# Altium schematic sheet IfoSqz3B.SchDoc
size C; Engineer: Daniel Sigg; DocumentNumber: 7; SheetNumber: 19; SheetTotal: 33
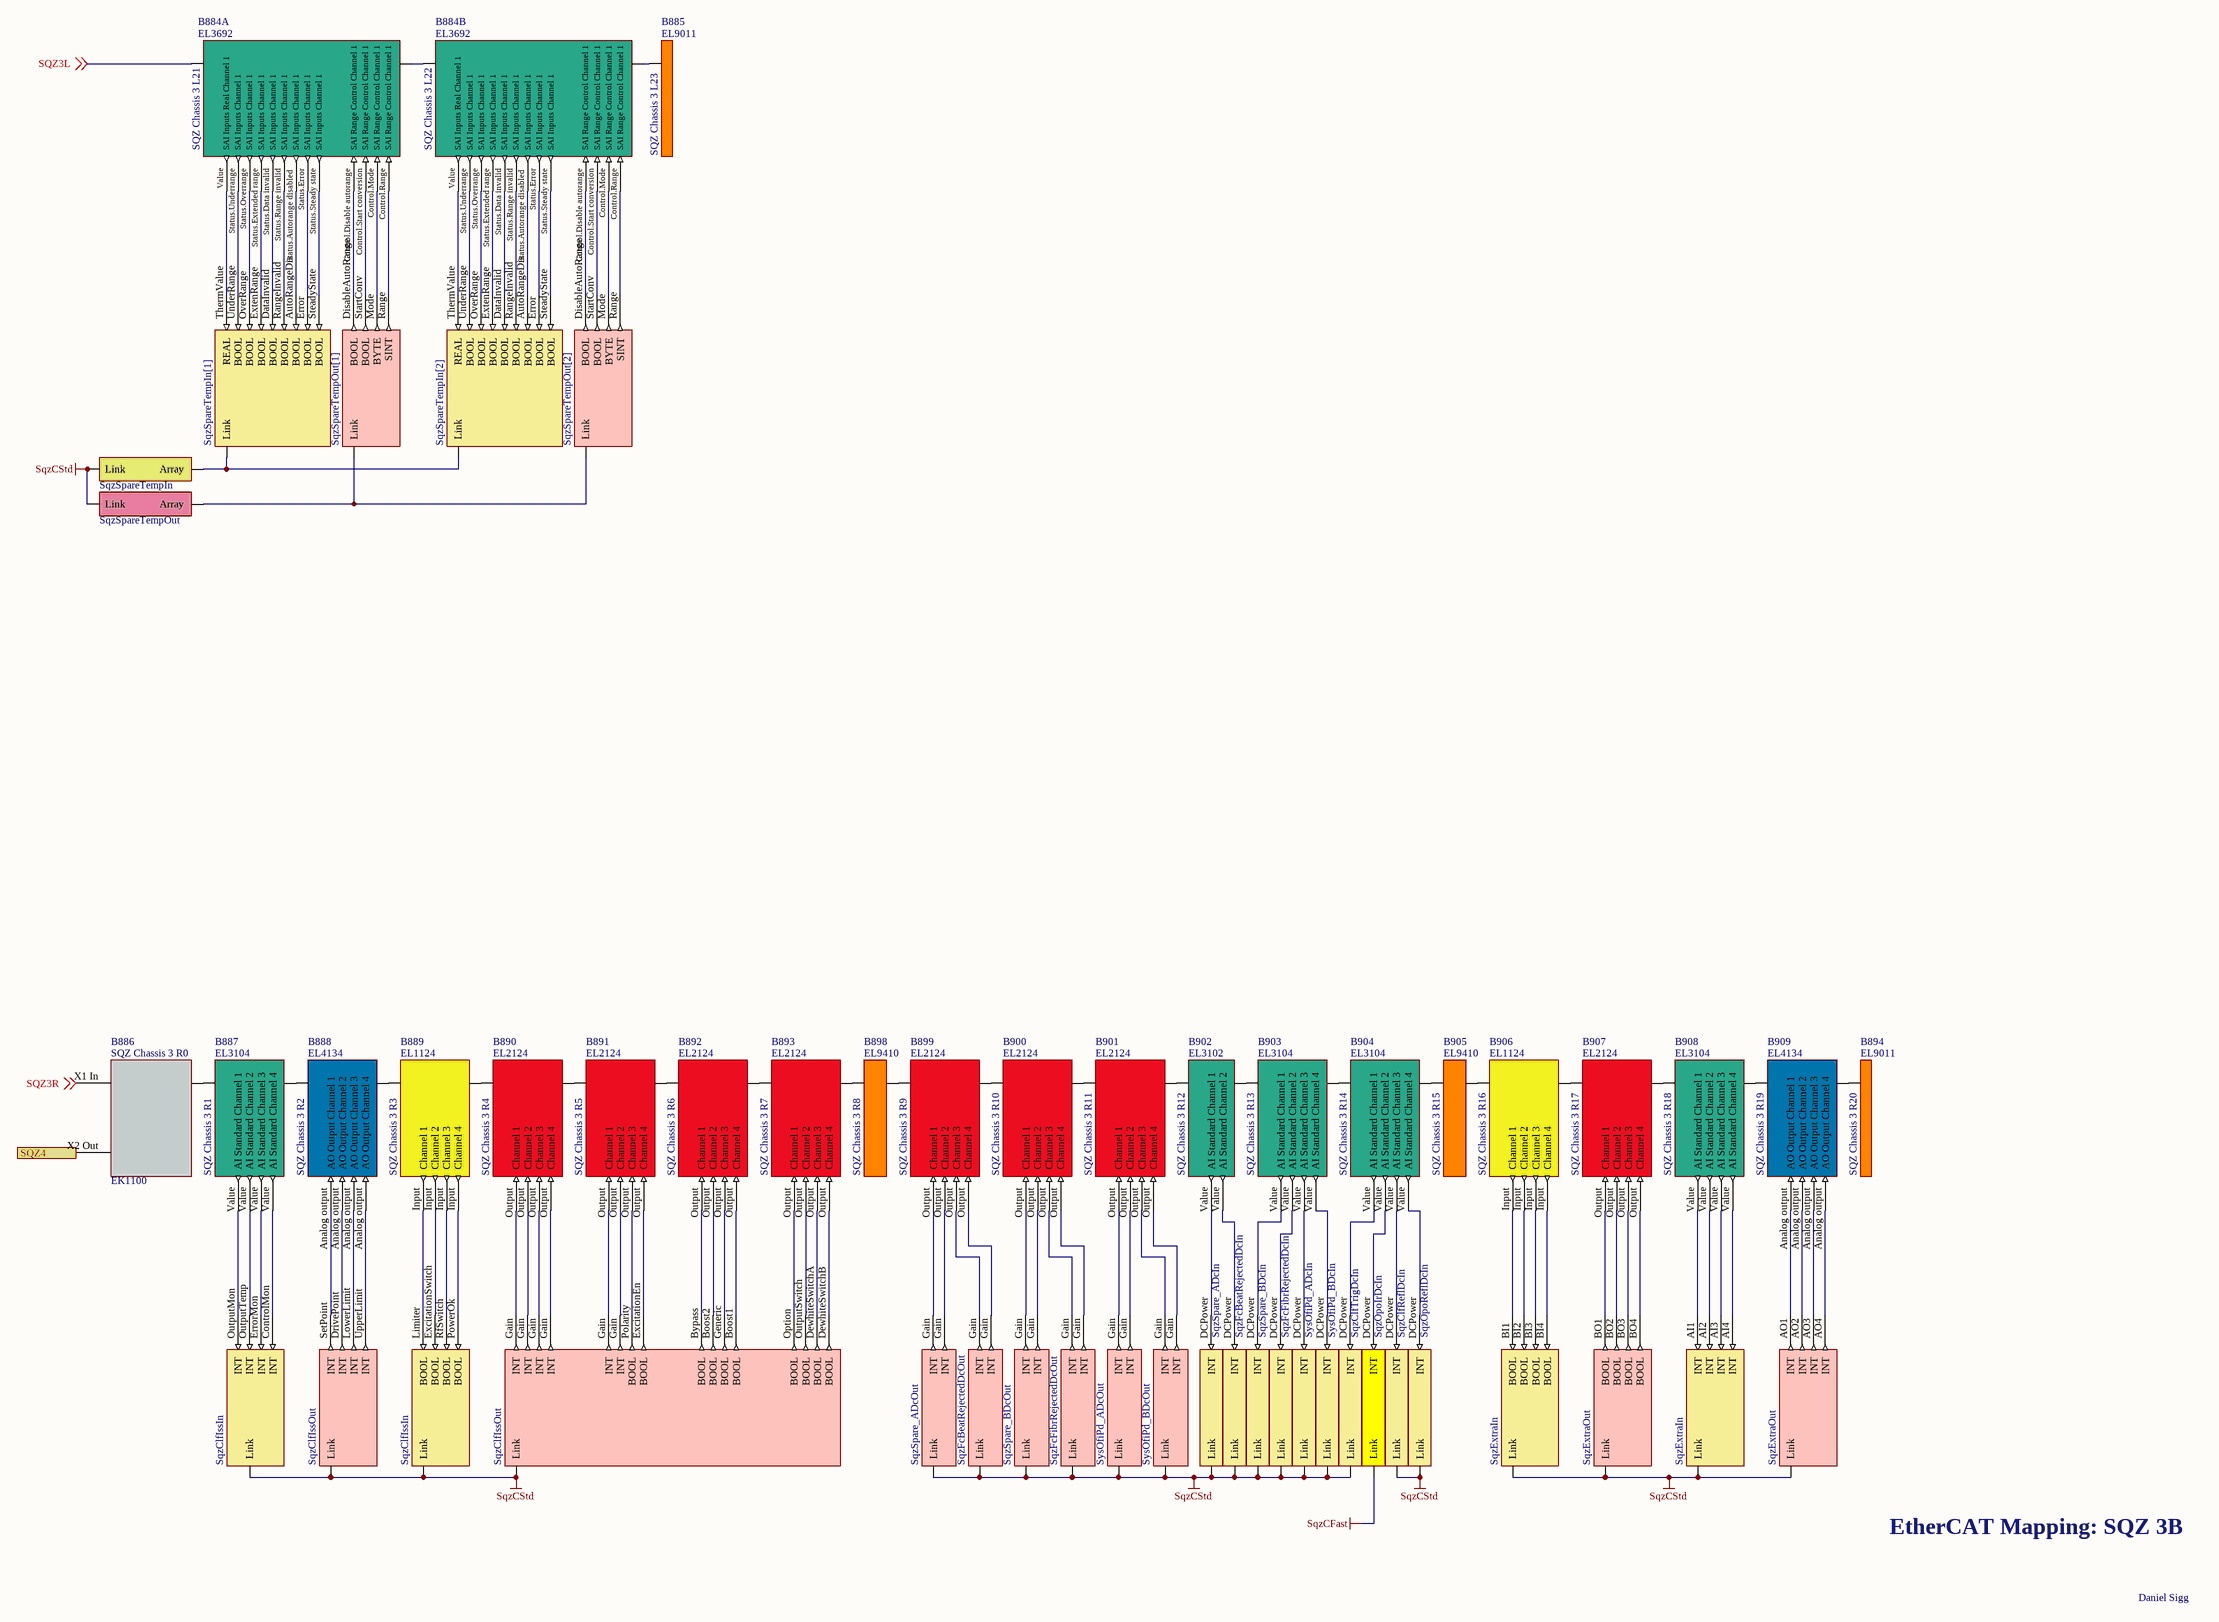
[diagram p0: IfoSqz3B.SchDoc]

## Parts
B884A  SQZ Chassis 3 L21  Part Number: EL3692  (mechanical)
B884B  SQZ Chassis 3 L22  Part Number: EL3692  (mechanical)
B885  SQZ Chassis 3 L23  Part Number: EL9011  (mechanical)
B886  SQZ Chassis 3 R0  Part Number: EK1100
B887  SQZ Chassis 3 R1  Part Number: EL3104  (mechanical)
B888  SQZ Chassis 3 R2  Part Number: EL4134  (mechanical)
B889  SQZ Chassis 3 R3  Part Number: EL1124  (mechanical)
B890  SQZ Chassis 3 R4  Part Number: EL2124  (mechanical)
B891  SQZ Chassis 3 R5  Part Number: EL2124  (mechanical)
B892  SQZ Chassis 3 R6  Part Number: EL2124  (mechanical)
B893  SQZ Chassis 3 R7  Part Number: EL2124  (mechanical)
B894  SQZ Chassis 3 R20  Part Number: EL9011  (mechanical)
B898  SQZ Chassis 3 R8  Part Number: EL9410  (mechanical)
B899  SQZ Chassis 3 R9  Part Number: EL2124  (mechanical)
B900  SQZ Chassis 3 R10  Part Number: EL2124  (mechanical)
B901  SQZ Chassis 3 R11  Part Number: EL2124  (mechanical)
B902  SQZ Chassis 3 R12  Part Number: EL3102  (mechanical)
B903  SQZ Chassis 3 R13  Part Number: EL3104  (mechanical)
B904  SQZ Chassis 3 R14  Part Number: EL3104  (mechanical)
B905  SQZ Chassis 3 R15  Part Number: EL9410  (mechanical)
B906  SQZ Chassis 3 R16  Part Number: EL1124  (mechanical)
B907  SQZ Chassis 3 R17  Part Number: EL2124  (mechanical)
B908  SQZ Chassis 3 R18  Part Number: EL3104  (mechanical)
B909  SQZ Chassis 3 R19  Part Number: EL4134  (mechanical)
V410  SqzClfIssIn  (parts A,B of 2)  (no BOM)
V411  SqzClfIssOut  (parts A,B of 2)  (no BOM)
V701  SqzSpareTempIn[1]  (no BOM)
V702  SqzSpareTempOut[1]  (no BOM)
V703  SqzSpareTempIn[2]  (no BOM)
V704  SqzSpareTempOut[2]  (no BOM)
V705  SqzSpareTempIn  (no BOM)
V706  SqzSpareTempOut  (no BOM)
V722  SqzSpare_ADcOut  (no BOM)
V723  SqzFcBeatRejectedDcOut  (no BOM)
V724  SqzFcFibrRejectedDcOut  (no BOM)
V725  SqzSpare_BDcOut  (no BOM)
V726  SysOfiPd_ADcOut  (no BOM)
V727  SysOfiPd_BDcOut  (no BOM)
V728  SqzSpare_ADcIn  (no BOM)
V729  SqzFcBeatRejectedDcIn  (no BOM)
V730  SqzFcFibrRejectedDcIn  (no BOM)
V731  SqzSpare_BDcIn  (no BOM)
V732  SysOfiPd_ADcIn  (no BOM)
V733  SysOfiPd_BDcIn  (no BOM)
V734  SqzClfTrigDcIn  (no BOM)
V735  SqzOpoIrDcIn  (no BOM)
V736  SqzClfReflDcIn  (no BOM)
V737  SqzOpoReflDcIn  (no BOM)
V738  SqzExtraIn  (parts A,B of 2)  (no BOM)
V739  SqzExtraOut  (parts A,B of 2)  (no BOM)

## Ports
SQZ4

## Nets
SqzCFast: V735.1(Link)
SqzCStd: V410.0(Link) V410.1(Link) V411.0(Link) V411.1(Link) V705.?1(Link) V706.?1(Link) V722.0(Link) V723.0(Link) V724.0(Link) V725.0(Link) V726.0(Link) V727.0(Link) V728.1(Link) V729.1(Link) V730.1(Link) V731.1(Link) V732.1(Link) V733.1(Link) V734.1(Link) V736.1(Link) V737.1(Link) V738.0(Link) V738.1(Link) V739.0(Link) V739.1(Link)
SQZ3L: B884A.Ebus(A) ; off-sheet SQZ3L
SQZ3R: B886.X1_In(A) ; off-sheet SQZ3R
SQZ4: B886.X2_Out(C) ; port SQZ4
NetB884A_Control.Disable autorange: B884A.Control.Disable_autorange(SAI_Range_Control_Channel_1) V702.DisableAutoRange(BOOL)
NetB884A_Control.Mode: B884A.Control.Mode(SAI_Range_Control_Channel_1) V702.Mode(BYTE)
NetB884A_Control.Range: B884A.Control.Range(SAI_Range_Control_Channel_1) V702.Range(SINT)
NetB884A_Control.Start conversion: B884A.Control.Start_conversion(SAI_Range_Control_Channel_1) V702.StartConv(BOOL)
NetB884A_Ebus: B884A.Ebus(B) B884B.Ebus(A)
NetB884A_Status.Autorange disabled: B884A.Status.Autorange_disabled(SAI_Inputs_Channel_1) V701.AutoRangeDis(BOOL)
NetB884A_Status.Data invalid: B884A.Status.Data_invalid(SAI_Inputs_Channel_1) V701.DataInvalid(BOOL)
NetB884A_Status.Error: B884A.Status.Error(SAI_Inputs_Channel_1) V701.Error(BOOL)
NetB884A_Status.Extended range: B884A.Status.Extended_range(SAI_Inputs_Channel_1) V701.ExtenRange(BOOL)
NetB884A_Status.Overrange: B884A.Status.Overrange(SAI_Inputs_Channel_1) V701.OverRange(BOOL)
NetB884A_Status.Range invalid: B884A.Status.Range_invalid(SAI_Inputs_Channel_1) V701.RangeInvalid(BOOL)
NetB884A_Status.Steady state: B884A.Status.Steady_state(SAI_Inputs_Channel_1) V701.SteadyState(BOOL)
NetB884A_Status.Underrange: B884A.Status.Underrange(SAI_Inputs_Channel_1) V701.UnderRange(BOOL)
NetB884A_Value: B884A.Value(SAI_Inputs_Real_Channel_1) V701.ThermValue(REAL)
NetB884B_Control.Disable autorange: B884B.Control.Disable_autorange(SAI_Range_Control_Channel_1) V704.DisableAutoRange(BOOL)
NetB884B_Control.Mode: B884B.Control.Mode(SAI_Range_Control_Channel_1) V704.Mode(BYTE)
NetB884B_Control.Range: B884B.Control.Range(SAI_Range_Control_Channel_1) V704.Range(SINT)
NetB884B_Control.Start conversion: B884B.Control.Start_conversion(SAI_Range_Control_Channel_1) V704.StartConv(BOOL)
NetB884B_Ebus: B884B.Ebus(B) B885.Ebus(A)
NetB884B_Status.Autorange disabled: B884B.Status.Autorange_disabled(SAI_Inputs_Channel_1) V703.AutoRangeDis(BOOL)
NetB884B_Status.Data invalid: B884B.Status.Data_invalid(SAI_Inputs_Channel_1) V703.DataInvalid(BOOL)
NetB884B_Status.Error: B884B.Status.Error(SAI_Inputs_Channel_1) V703.Error(BOOL)
NetB884B_Status.Extended range: B884B.Status.Extended_range(SAI_Inputs_Channel_1) V703.ExtenRange(BOOL)
NetB884B_Status.Overrange: B884B.Status.Overrange(SAI_Inputs_Channel_1) V703.OverRange(BOOL)
NetB884B_Status.Range invalid: B884B.Status.Range_invalid(SAI_Inputs_Channel_1) V703.RangeInvalid(BOOL)
NetB884B_Status.Steady state: B884B.Status.Steady_state(SAI_Inputs_Channel_1) V703.SteadyState(BOOL)
NetB884B_Status.Underrange: B884B.Status.Underrange(SAI_Inputs_Channel_1) V703.UnderRange(BOOL)
NetB884B_Value: B884B.Value(SAI_Inputs_Real_Channel_1) V703.ThermValue(REAL)
NetB886_Ebus: B886.Ebus(B) B887.Ebus(A)
NetB887_Ebus: B887.Ebus(B) B888.Ebus(A)
NetB887_Value: B887.Value(AI_Standard_Channel_1) V410.OutputMon(INT)
NetB887_Value: B887.Value(AI_Standard_Channel_2) V410.OutputTemp(INT)  [a separate net that carries the same name]
NetB887_Value: B887.Value(AI_Standard_Channel_3) V410.ErrorMon(INT)  [a separate net that carries the same name]
NetB887_Value: B887.Value(AI_Standard_Channel_4) V410.ControlMon(INT)  [a separate net that carries the same name]
NetB888_Analog output: B888.Analog_output(AO_Output_Channel_1) V411.SetPoint(INT)
NetB888_Analog output: B888.Analog_output(AO_Output_Channel_2) V411.DrivePoint(INT)  [a separate net that carries the same name]
NetB888_Analog output: B888.Analog_output(AO_Output_Channel_3) V411.LowerLimit(INT)  [a separate net that carries the same name]
NetB888_Analog output: B888.Analog_output(AO_Output_Channel_4) V411.UpperLimit(INT)  [a separate net that carries the same name]
NetB888_Ebus: B888.Ebus(B) B889.Ebus(A)
NetB889_Ebus: B889.Ebus(B) B890.Ebus(A)
NetB889_Input: B889.Input(Channel_1) V410.Limiter(BOOL)
NetB889_Input: B889.Input(Channel_2) V410.ExcitationSwitch(BOOL)  [a separate net that carries the same name]
NetB889_Input: B889.Input(Channel_3) V410.RfSwitch(BOOL)  [a separate net that carries the same name]
NetB889_Input: B889.Input(Channel_4) V410.PowerOk(BOOL)  [a separate net that carries the same name]
NetB890_Ebus: B890.Ebus(B) B891.Ebus(A)
NetB890_Output: B890.Output(Channel_1) V411.Gain(INT)
NetB890_Output: B890.Output(Channel_2) V411.Gain(INT)  [a separate net that carries the same name]
NetB890_Output: B890.Output(Channel_3) V411.Gain(INT)  [a separate net that carries the same name]
NetB890_Output: B890.Output(Channel_4) V411.Gain(INT)  [a separate net that carries the same name]
NetB891_Ebus: B891.Ebus(B) B892.Ebus(A)
NetB891_Output: B891.Output(Channel_1) V411.Gain(INT)
NetB891_Output: B891.Output(Channel_2) V411.Gain(INT)  [a separate net that carries the same name]
NetB891_Output: B891.Output(Channel_3) V411.Polarity(BOOL)  [a separate net that carries the same name]
NetB891_Output: B891.Output(Channel_4) V411.ExcitationEn(BOOL)  [a separate net that carries the same name]
NetB892_Ebus: B892.Ebus(B) B893.Ebus(A)
NetB892_Output: B892.Output(Channel_1) V411.Bypass(BOOL)
NetB892_Output: B892.Output(Channel_2) V411.Boost2(BOOL)  [a separate net that carries the same name]
NetB892_Output: B892.Output(Channel_3) V411.Generic(BOOL)  [a separate net that carries the same name]
NetB892_Output: B892.Output(Channel_4) V411.Boost1(BOOL)  [a separate net that carries the same name]
NetB893_Ebus: B893.Ebus(B) B898.Ebus(A)
NetB893_Output: B893.Output(Channel_1) V411.Option(BOOL)
NetB893_Output: B893.Output(Channel_2) V411.OutputSwitch(BOOL)  [a separate net that carries the same name]
NetB893_Output: B893.Output(Channel_3) V411.DewhiteSwitchA(BOOL)  [a separate net that carries the same name]
NetB893_Output: B893.Output(Channel_4) V411.DewhiteSwitchB(BOOL)  [a separate net that carries the same name]
NetB894_Ebus: B894.Ebus(A) B909.Ebus(B)
NetB898_Ebus: B898.Ebus(B) B899.Ebus(A)
NetB899_Ebus: B899.Ebus(B) B900.Ebus(A)
NetB899_Output: B899.Output(Channel_1) V722.Gain(INT)
NetB899_Output: B899.Output(Channel_2) V722.Gain(INT)  [a separate net that carries the same name]
NetB899_Output: B899.Output(Channel_3) V723.Gain(INT)  [a separate net that carries the same name]
NetB899_Output: B899.Output(Channel_4) V723.Gain(INT)  [a separate net that carries the same name]
NetB900_Ebus: B900.Ebus(B) B901.Ebus(A)
NetB900_Output: B900.Output(Channel_1) V725.Gain(INT)
NetB900_Output: B900.Output(Channel_2) V725.Gain(INT)  [a separate net that carries the same name]
NetB900_Output: B900.Output(Channel_3) V724.Gain(INT)  [a separate net that carries the same name]
NetB900_Output: B900.Output(Channel_4) V724.Gain(INT)  [a separate net that carries the same name]
NetB901_Ebus: B901.Ebus(B) B902.Ebus(A)
NetB901_Output: B901.Output(Channel_1) V726.Gain(INT)
NetB901_Output: B901.Output(Channel_2) V726.Gain(INT)  [a separate net that carries the same name]
NetB901_Output: B901.Output(Channel_3) V727.Gain(INT)  [a separate net that carries the same name]
NetB901_Output: B901.Output(Channel_4) V727.Gain(INT)  [a separate net that carries the same name]
NetB902_Ebus: B902.Ebus(B) B903.Ebus(A)
NetB902_Value: B902.Value(AI_Standard_Channel_1) V728.DCPower(INT)
NetB902_Value: B902.Value(AI_Standard_Channel_2) V729.DCPower(INT)  [a separate net that carries the same name]
NetB903_Ebus: B903.Ebus(B) B904.Ebus(A)
NetB903_Value: B903.Value(AI_Standard_Channel_1) V731.DCPower(INT)
NetB903_Value: B903.Value(AI_Standard_Channel_2) V730.DCPower(INT)  [a separate net that carries the same name]
NetB903_Value: B903.Value(AI_Standard_Channel_3) V732.DCPower(INT)  [a separate net that carries the same name]
NetB903_Value: B903.Value(AI_Standard_Channel_4) V733.DCPower(INT)  [a separate net that carries the same name]
NetB904_Ebus: B904.Ebus(B) B905.Ebus(A)
NetB904_Value: B904.Value(AI_Standard_Channel_1) V734.DCPower(INT)
NetB904_Value: B904.Value(AI_Standard_Channel_2) V735.DCPower(INT)  [a separate net that carries the same name]
NetB904_Value: B904.Value(AI_Standard_Channel_3) V736.DCPower(INT)  [a separate net that carries the same name]
NetB904_Value: B904.Value(AI_Standard_Channel_4) V737.DCPower(INT)  [a separate net that carries the same name]
NetB905_Ebus: B905.Ebus(B) B906.Ebus(A)
NetB906_Ebus: B906.Ebus(B) B907.Ebus(A)
NetB906_Input: B906.Input(Channel_1) V738.BI1(BOOL)
NetB906_Input: B906.Input(Channel_2) V738.BI2(BOOL)  [a separate net that carries the same name]
NetB906_Input: B906.Input(Channel_3) V738.BI3(BOOL)  [a separate net that carries the same name]
NetB906_Input: B906.Input(Channel_4) V738.BI4(BOOL)  [a separate net that carries the same name]
NetB907_Ebus: B907.Ebus(B) B908.Ebus(A)
NetB907_Output: B907.Output(Channel_1) V739.BO1(BOOL)
NetB907_Output: B907.Output(Channel_2) V739.BO2(BOOL)  [a separate net that carries the same name]
NetB907_Output: B907.Output(Channel_3) V739.BO3(BOOL)  [a separate net that carries the same name]
NetB907_Output: B907.Output(Channel_4) V739.BO4(BOOL)  [a separate net that carries the same name]
NetB908_Ebus: B908.Ebus(B) B909.Ebus(A)
NetB908_Value: B908.Value(AI_Standard_Channel_1) V738.AI1(INT)
NetB908_Value: B908.Value(AI_Standard_Channel_2) V738.AI2(INT)  [a separate net that carries the same name]
NetB908_Value: B908.Value(AI_Standard_Channel_3) V738.AI3(INT)  [a separate net that carries the same name]
NetB908_Value: B908.Value(AI_Standard_Channel_4) V738.AI4(INT)  [a separate net that carries the same name]
NetB909_Analog output: B909.Analog_output(AO_Output_Channel_1) V739.AO1(INT)
NetB909_Analog output: B909.Analog_output(AO_Output_Channel_2) V739.AO2(INT)  [a separate net that carries the same name]
NetB909_Analog output: B909.Analog_output(AO_Output_Channel_3) V739.AO3(INT)  [a separate net that carries the same name]
NetB909_Analog output: B909.Analog_output(AO_Output_Channel_4) V739.AO4(INT)  [a separate net that carries the same name]
NetV701_1: V701.1(Link) V703.1(Link) V705.?2(Array)
NetV702_1: V702.1(Link) V704.1(Link) V706.?2(Array)

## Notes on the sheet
- EtherCAT Mapping: SQZ 3B
- Daniel Sigg

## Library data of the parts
B884A = TerminalEL3692-1chn: EtherCAT Terminal EL3692 1-chn Resistance Measurement; Rail: Left; BoxNextB: HCCQCWHL; BoxPrev: FHTRRYRM; PortPrevFull: 1141/B; PortPrevShort: B; Fullname: TIID^Vertex Squeezer (EtherCAT)^SQZ Chassis 3 L0 (EK1101)^SQZ Chassis 3 L21 (EL3692); BoxAddr: 1142; PDO Inputs: 0x1A00,0x1A02; PDO Outputs: 0x1600; Disabled: False
B884B = TerminalEL3692-1chn: EtherCAT Terminal EL3692 1-chn Resistance Measurement; Rail: Left; BoxNextB: CYSUGKJU; BoxPrev: BXXLOSJW; PortPrevFull: 1142/B; PortPrevShort: B; Fullname: TIID^Vertex Squeezer (EtherCAT)^SQZ Chassis 3 L0 (EK1101)^SQZ Chassis 3 L22 (EL3692); BoxAddr: 1143; PDO Inputs: 0x1A00,0x1A02; PDO Outputs: 0x1600; Disabled: False
B885 = TerminalEL9011: EtherCAT Terminal EL9011 End; BoxType: TerminalPassive; Rail: Left; BoxPrev: HCCQCWHL; PortPrevShort: B; Fullname: TIID^Vertex Squeezer (EtherCAT)^SQZ Chassis 3 L0 (EK1101)^SQZ Chassis 3 L23 (EL9011); Disabled: False
B886 = CouplerEK1100: EtherCAT Coupler; Rail: Right; BoxNextB: LMNHRKFK; BoxNextC: BCNOLNHC; BoxPrev: VQWTFMVH; PortPrevFull: 1144/C; PortPrevShort: C 'X2 Out'; Fullname: TIID^Vertex Squeezer (EtherCAT)^SQZ Chassis 3 R0 (EK1100); BoxPorts: Junction; BoxAddr: 1168; Disabled: False
B887 = TerminalEL3104: EtherCAT Terminal EL3104 4-chn Analog Input; Rail: Right; BoxNextB: SAJIWMHJ; BoxPrev: BKUDMEPV; PortPrevFull: 1168/B; PortPrevShort: B; Fullname: TIID^Vertex Squeezer (EtherCAT)^SQZ Chassis 3 R0 (EK1100)^SQZ Chassis 3 R1 (EL3104); BoxAddr: 1169; Disabled: False
B888 = TerminalEL4134: EtherCAT Terminal EL4134 4-chn Analog Ouput; Rail: Right; BoxNextB: JGBHBNGR; BoxPrev: LMNHRKFK; PortPrevFull: 1169/B; PortPrevShort: B; Fullname: TIID^Vertex Squeezer (EtherCAT)^SQZ Chassis 3 R0 (EK1100)^SQZ Chassis 3 R2 (EL4134); BoxAddr: 1170; Disabled: False
B889 = TerminalEL1124: EtherCAT Terminal EL1124 4-chn Digital Input; Rail: Right; BoxNextB: VKBNNKDD; BoxPrev: SAJIWMHJ; PortPrevFull: 1170/B; PortPrevShort: B; Fullname: TIID^Vertex Squeezer (EtherCAT)^SQZ Chassis 3 R0 (EK1100)^SQZ Chassis 3 R3 (EL1124); BoxAddr: 1171; Disabled: False
B890 = TerminalEL2124: EtherCAT Terminal EL2124 4-chn Digital Ouput; Rail: Right; BoxNextB: CQYTOJCV; BoxPrev: JGBHBNGR; PortPrevFull: 1171/B; PortPrevShort: B; Fullname: TIID^Vertex Squeezer (EtherCAT)^SQZ Chassis 3 R0 (EK1100)^SQZ Chassis 3 R4 (EL2124); BoxAddr: 1172; Disabled: False
B891 = TerminalEL2124: EtherCAT Terminal EL2124 4-chn Digital Ouput; Rail: Right; BoxNextB: GUINYQMW; BoxPrev: VKBNNKDD; PortPrevFull: 1172/B; PortPrevShort: B; Fullname: TIID^Vertex Squeezer (EtherCAT)^SQZ Chassis 3 R0 (EK1100)^SQZ Chassis 3 R5 (EL2124); BoxAddr: 1173; Disabled: False
B892 = TerminalEL2124: EtherCAT Terminal EL2124 4-chn Digital Ouput; Rail: Right; BoxNextB: HMWVQJTD; BoxPrev: CQYTOJCV; PortPrevFull: 1173/B; PortPrevShort: B; Fullname: TIID^Vertex Squeezer (EtherCAT)^SQZ Chassis 3 R0 (EK1100)^SQZ Chassis 3 R6 (EL2124); BoxAddr: 1174; Disabled: False
B893 = TerminalEL2124: EtherCAT Terminal EL2124 4-chn Digital Ouput; Rail: Right; BoxNextB: EWXBFFSC; BoxPrev: GUINYQMW; PortPrevFull: 1174/B; PortPrevShort: B; Fullname: TIID^Vertex Squeezer (EtherCAT)^SQZ Chassis 3 R0 (EK1100)^SQZ Chassis 3 R7 (EL2124); BoxAddr: 1175; Disabled: False
B894 = TerminalEL9011: EtherCAT Terminal EL9011 End; BoxType: TerminalPassive; Rail: Right; BoxPrev: REDTJCGQ; PortPrevShort: B; Fullname: TIID^Vertex Squeezer (EtherCAT)^SQZ Chassis 3 R0 (EK1100)^SQZ Chassis 3 R20 (EL9011); Disabled: False
B898 = TerminalEL9410: EtherCAT Terminal EL9410 Power; Rail: Right; BoxNextB: TDWNLRLC; BoxPrev: HMWVQJTD; PortPrevFull: 1175/B; PortPrevShort: B; Fullname: TIID^Vertex Squeezer (EtherCAT)^SQZ Chassis 3 R0 (EK1100)^SQZ Chassis 3 R8 (EL9410); BoxAddr: 1176; Disabled: False
B899 = TerminalEL2124: EtherCAT Terminal EL2124 4-chn Digital Ouput; Rail: Right; BoxNextB: JKJTFGCV; BoxPrev: EWXBFFSC; PortPrevFull: 1176/B; PortPrevShort: B; Fullname: TIID^Vertex Squeezer (EtherCAT)^SQZ Chassis 3 R0 (EK1100)^SQZ Chassis 3 R9 (EL2124); BoxAddr: 1177; Disabled: False
B900 = TerminalEL2124: EtherCAT Terminal EL2124 4-chn Digital Ouput; Rail: Right; BoxNextB: YYBAPAKS; BoxPrev: TDWNLRLC; PortPrevFull: 1177/B; PortPrevShort: B; Fullname: TIID^Vertex Squeezer (EtherCAT)^SQZ Chassis 3 R0 (EK1100)^SQZ Chassis 3 R10 (EL2124); BoxAddr: 1178; Disabled: False
B901 = TerminalEL2124: EtherCAT Terminal EL2124 4-chn Digital Ouput; Rail: Right; BoxNextB: KULEGXXY; BoxPrev: JKJTFGCV; PortPrevFull: 1178/B; PortPrevShort: B; Fullname: TIID^Vertex Squeezer (EtherCAT)^SQZ Chassis 3 R0 (EK1100)^SQZ Chassis 3 R11 (EL2124); BoxAddr: 1179; Disabled: False
B902 = TerminalEL3102: EtherCAT Terminal EL3102 2-chn Analog Input; Rail: Right; BoxNextB: QOIJDIEC; BoxPrev: YYBAPAKS; PortPrevFull: 1179/B; PortPrevShort: B; Fullname: TIID^Vertex Squeezer (EtherCAT)^SQZ Chassis 3 R0 (EK1100)^SQZ Chassis 3 R12 (EL3102); BoxAddr: 1180; Disabled: False
B903 = TerminalEL3104: EtherCAT Terminal EL3104 4-chn Analog Input; Rail: Right; BoxNextB: XSWHLOWF; BoxPrev: KULEGXXY; PortPrevFull: 1180/B; PortPrevShort: B; Fullname: TIID^Vertex Squeezer (EtherCAT)^SQZ Chassis 3 R0 (EK1100)^SQZ Chassis 3 R13 (EL3104); BoxAddr: 1181; Disabled: False
B904 = TerminalEL3104: EtherCAT Terminal EL3104 4-chn Analog Input; Rail: Right; BoxNextB: DXXDEXAW; BoxPrev: QOIJDIEC; PortPrevFull: 1181/B; PortPrevShort: B; Fullname: TIID^Vertex Squeezer (EtherCAT)^SQZ Chassis 3 R0 (EK1100)^SQZ Chassis 3 R14 (EL3104); BoxAddr: 1182; Disabled: False
B905 = TerminalEL9410: EtherCAT Terminal EL9410 Power; Rail: Right; BoxNextB: LQYWWYRA; BoxPrev: XSWHLOWF; PortPrevFull: 1182/B; PortPrevShort: B; Fullname: TIID^Vertex Squeezer (EtherCAT)^SQZ Chassis 3 R0 (EK1100)^SQZ Chassis 3 R15 (EL9410); BoxAddr: 1183; Disabled: False
B906 = TerminalEL1124: EtherCAT Terminal EL1124 4-chn Digital Input; Rail: Right; BoxNextB: KAAFGPDB; BoxPrev: DXXDEXAW; PortPrevFull: 1183/B; PortPrevShort: B; Fullname: TIID^Vertex Squeezer (EtherCAT)^SQZ Chassis 3 R0 (EK1100)^SQZ Chassis 3 R16 (EL1124); BoxAddr: 1184; Disabled: False
B907 = TerminalEL2124: EtherCAT Terminal EL2124 4-chn Digital Ouput; Rail: Right; BoxNextB: YRGWWXTI; BoxPrev: LQYWWYRA; PortPrevFull: 1184/B; PortPrevShort: B; Fullname: TIID^Vertex Squeezer (EtherCAT)^SQZ Chassis 3 R0 (EK1100)^SQZ Chassis 3 R17 (EL2124); BoxAddr: 1185; Disabled: False
B908 = TerminalEL3104: EtherCAT Terminal EL3104 4-chn Analog Input; Rail: Right; BoxNextB: REDTJCGQ; BoxPrev: KAAFGPDB; PortPrevFull: 1185/B; PortPrevShort: B; Fullname: TIID^Vertex Squeezer (EtherCAT)^SQZ Chassis 3 R0 (EK1100)^SQZ Chassis 3 R18 (EL3104); BoxAddr: 1186; Disabled: False
B909 = TerminalEL4134: EtherCAT Terminal EL4134 4-chn Analog Ouput; Rail: Right; BoxNextB: RXFIDCPJ; BoxPrev: YRGWWXTI; PortPrevFull: 1186/B; PortPrevShort: B; Fullname: TIID^Vertex Squeezer (EtherCAT)^SQZ Chassis 3 R0 (EK1100)^SQZ Chassis 3 R19 (EL4134); BoxAddr: 1187; Disabled: False
V410 = Iss_AomServoInStruct: AomServoInStruct; BoxType: Variable; Instance: H1SqzCorner Instance; PLC: H1SqzCorner; Task: SqzCStd
V411 = Iss_AomServoOutStruct: AomServoOutStruct; BoxType: Variable; Instance: H1SqzCorner Instance; PLC: H1SqzCorner; Task: SqzCStd
V701 V703 = TECController_ThermistorInStruct: ThermistorInStruct; BoxType: Variable; Instance: H1SqzCorner Instance; PLC: H1SqzCorner; Task: SqzCStd
V702 V704 = TECController_ThermistorOutStruct: ThermistorOutStruct; BoxType: Variable; Instance: H1SqzCorner Instance; PLC: H1SqzCorner; Task: SqzCStd
V705 = ArrayAggregatorIn: Array [1..2] Of ThermistorInStruct; Instance: H1SqzCorner Instance; PLC: H1SqzCorner; Task: SqzCStd; Lower Bound: 1; Upper Bound: 2
V706 = ArrayAggregatorOut: Array [1..2] Of ThermistorOutStruct; Instance: H1SqzCorner Instance; PLC: H1SqzCorner; Task: SqzCStd; Lower Bound: 1; Upper Bound: 2
V722-V727 = DCPower_DCPowerOutStruct: DCPowerOutStruct; BoxType: Variable; Instance: H1SqzCorner Instance; PLC: H1SqzCorner; Task: SqzCStd
V728-V734 V736 V737 = DCPower_DCPowerInStruct: DCPowerInStruct; BoxType: Variable; Instance: H1SqzCorner Instance; PLC: H1SqzCorner; Task: SqzCStd
V735 = DCPower_DCPowerFastInStruct: DCPowerInStruct; BoxType: Variable; Instance: H1SqzCorner Instance; PLC: H1SqzCorner; Task: SqzCFast
V738 = Auxiliary_AuxiliaryInStruct: AuxiliaryInStruct; BoxType: Variable; Instance: H1SqzCorner Instance; PLC: H1SqzCorner; Task: SqzCStd
V739 = Auxiliary_AuxiliaryOutStruct: AuxiliaryOutStruct; BoxType: Variable; Instance: H1SqzCorner Instance; PLC: H1SqzCorner; Task: SqzCStd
